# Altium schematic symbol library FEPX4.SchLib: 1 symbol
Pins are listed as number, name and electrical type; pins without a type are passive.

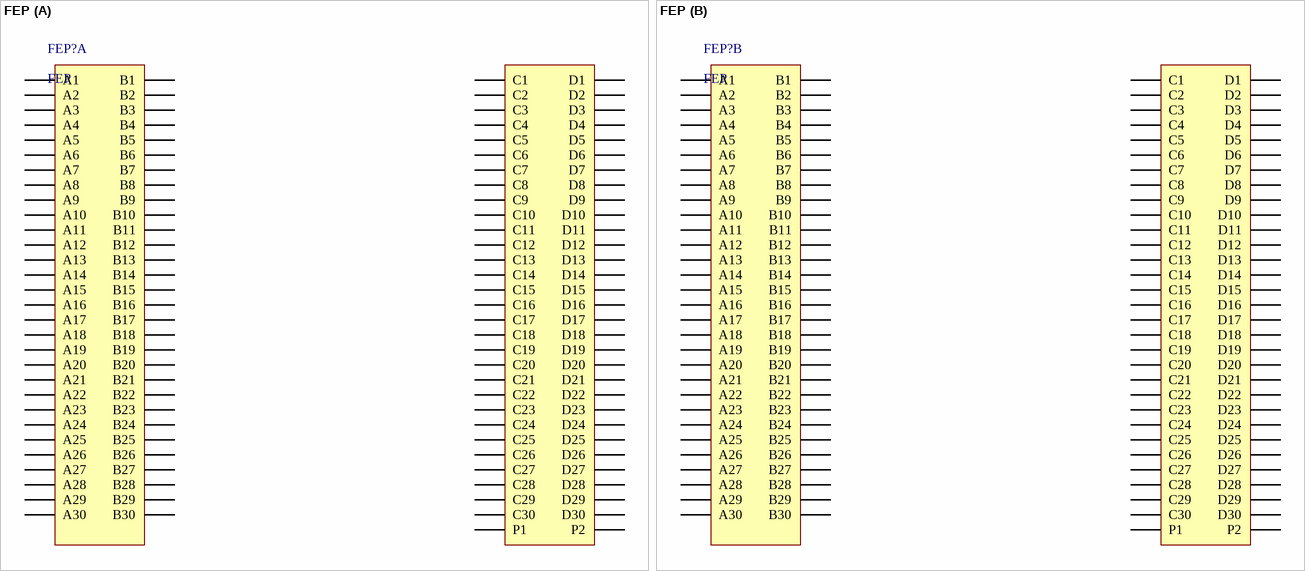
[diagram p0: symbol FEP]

## FEP
designator FEP?
footprint FEPX4C
footprint FEPX4M
part A pins: 1A1 A1, 1A2 A2, 1A3 A3, 1A4 A4, 1A5 A5, 1A6 A6, 1A7 A7, 1A8 A8, 1A9 A9, 1A10 A10, 1A11 A11, 1A12 A12, 1A13 A13, 1A14 A14, 1A15 A15, 1A16 A16, 1A17 A17, 1A18 A18, 1A19 A19, 1A20 A20, 1A21 A21, 1A22 A22, 1A23 A23, 1A24 A24, 1A25 A25, 1A26 A26, 1A27 A27, 1A28 A28, 1A29 A29, 1A30 A30, 1B1 B1, 1B2 B2, 1B3 B3, 1B4 B4, 1B5 B5, 1B6 B6, 1B7 B7, 1B8 B8, 1B9 B9, 1B10 B10, 1B11 B11, 1B12 B12, 1B13 B13, 1B14 B14, 1B15 B15, 1B16 B16, 1B17 B17, 1B18 B18, 1B19 B19, 1B20 B20, 1B21 B21, 1B22 B22, 1B23 B23, 1B24 B24, 1B25 B25, 1B26 B26, 1B27 B27, 1B28 B28, 1B29 B29, 1B30 B30, 1C1 C1, 1C2 C2, 1C3 C3, 1C4 C4, 1C5 C5, 1C6 C6, 1C7 C7, 1C8 C8, 1C9 C9, 1C10 C10, 1C11 C11, 1C12 C12, 1C13 C13, 1C14 C14, 1C15 C15, 1C16 C16, 1C17 C17, 1C18 C18, 1C19 C19, 1C20 C20, 1C21 C21, 1C22 C22, 1C23 C23, 1C24 C24, 1C25 C25, 1C26 C26, 1C27 C27, 1C28 C28, 1C29 C29, 1C30 C30, 1D1 D1, 1D2 D2, 1D3 D3, 1D4 D4, 1D5 D5, 1D6 D6, 1D7 D7, 1D8 D8, 1D9 D9, 1D10 D10, 1D11 D11, 1D12 D12, 1D13 D13, 1D14 D14, 1D15 D15, 1D16 D16, 1D17 D17, 1D18 D18, 1D19 D19, 1D20 D20, 1D21 D21, 1D22 D22, 1D23 D23, 1D24 D24, 1D25 D25, 1D26 D26, 1D27 D27, 1D28 D28, 1D29 D29, 1D30 D30, 1P1 P1, 1P2 P2
part B pins: 2A1 A1, 2A2 A2, 2A3 A3, 2A4 A4, 2A5 A5, 2A6 A6, 2A7 A7, 2A8 A8, 2A9 A9, 2A10 A10, 2A11 A11, 2A12 A12, 2A13 A13, 2A14 A14, 2A15 A15, 2A16 A16, 2A17 A17, 2A18 A18, 2A19 A19, 2A20 A20, 2A21 A21, 2A22 A22, 2A23 A23, 2A24 A24, 2A25 A25, 2A26 A26, 2A27 A27, 2A28 A28, 2A29 A29, 2A30 A30, 2B1 B1, 2B2 B2, 2B3 B3, 2B4 B4, 2B5 B5, 2B6 B6, 2B7 B7, 2B8 B8, 2B9 B9, 2B10 B10, 2B11 B11, 2B12 B12, 2B13 B13, 2B14 B14, 2B15 B15, 2B16 B16, 2B17 B17, 2B18 B18, 2B19 B19, 2B20 B20, 2B21 B21, 2B22 B22, 2B23 B23, 2B24 B24, 2B25 B25, 2B26 B26, 2B27 B27, 2B28 B28, 2B29 B29, 2B30 B30, 2C1 C1, 2C2 C2, 2C3 C3, 2C4 C4, 2C5 C5, 2C6 C6, 2C7 C7, 2C8 C8, 2C9 C9, 2C10 C10, 2C11 C11, 2C12 C12, 2C13 C13, 2C14 C14, 2C15 C15, 2C16 C16, 2C17 C17, 2C18 C18, 2C19 C19, 2C20 C20, 2C21 C21, 2C22 C22, 2C23 C23, 2C24 C24, 2C25 C25, 2C26 C26, 2C27 C27, 2C28 C28, 2C29 C29, 2C30 C30, 2D1 D1, 2D2 D2, 2D3 D3, 2D4 D4, 2D5 D5, 2D6 D6, 2D7 D7, 2D8 D8, 2D9 D9, 2D10 D10, 2D11 D11, 2D12 D12, 2D13 D13, 2D14 D14, 2D15 D15, 2D16 D16, 2D17 D17, 2D18 D18, 2D19 D19, 2D20 D20, 2D21 D21, 2D22 D22, 2D23 D23, 2D24 D24, 2D25 D25, 2D26 D26, 2D27 D27, 2D28 D28, 2D29 D29, 2D30 D30, 2P1 P1, 2P2 P2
